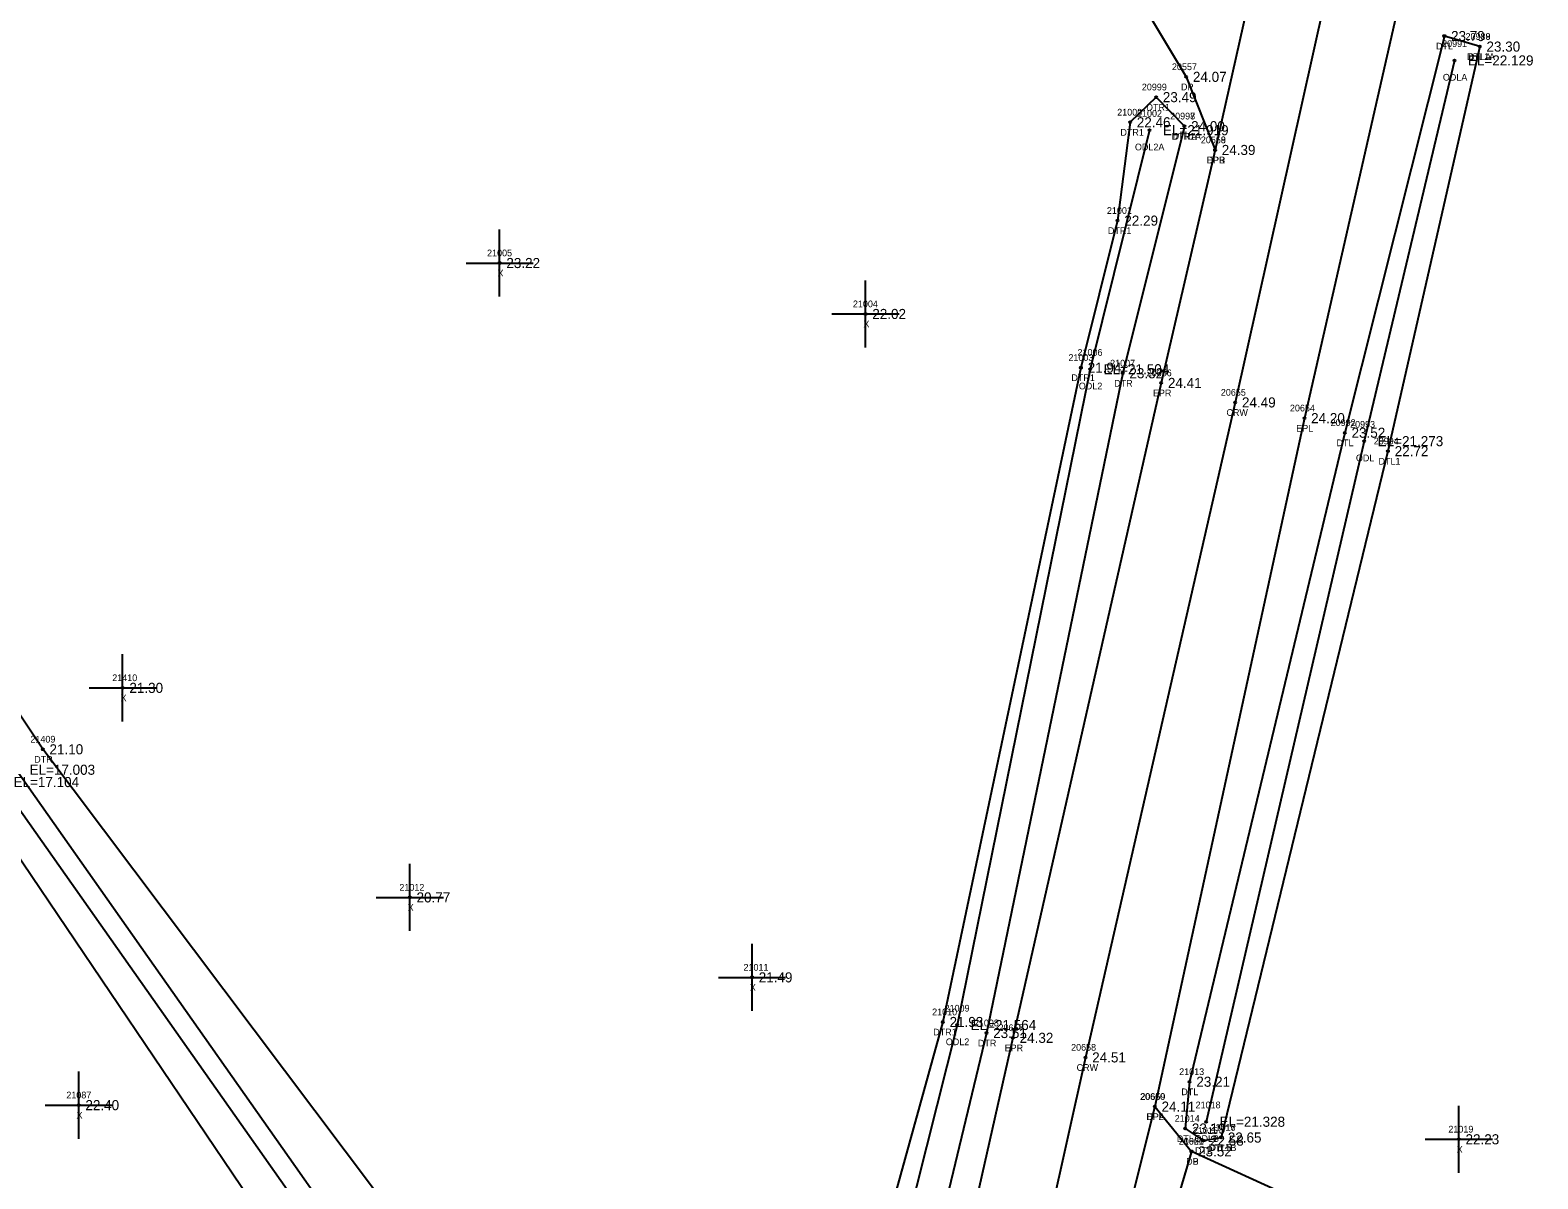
# Model space of a CAD drawing. Extents: x 2655177 to 2656219, y 761780 to 764748.
# Drawn here: x 2655371.8 to 2655596.2, y 762404.1 to 762575 of the extents above; entities that cross this region are included whole.
import ezdxf

# ---------------------------------------------------------------- set-up
doc = ezdxf.new("R2010")
doc.units = 0
for name, color, linetype in [('RD_DTM_BkLn1', 7, 'Continuous'), ('RD_EX_Driveway', 7, 'Continuous'), ('RD_EX_Driveway_txCode', 7, 'Continuous'), ('RD_EX_H2O', 7, 'Continuous'), ('RD_EX_H2O_txCode', 7, 'Continuous'), ('RD_EX_Misc', 7, 'Continuous'), ('RD_EX_Misc_txCode', 7, 'Continuous'), ('RD_EX_Road', 7, 'Continuous'), ('RD_EX_Road_txCode', 7, 'Continuous'), ('RD_EX_TX_Driveway_ELEV', 7, 'Continuous'), ('RD_EX_TX_H2O_ELEV', 7, 'Continuous'), ('RD_EX_TX_Misc_ELEV', 7, 'Continuous'), ('RD_EX_TX_Road_ELEV', 7, 'Continuous'), ('RD_HC_Survey_ELEV', 7, 'Continuous'), ('RD_HC_Survey_txCode', 7, 'Continuous'), ('RD_SMD_Locator', 7, 'Continuous')]:
    doc.layers.add(name, color=color, linetype=linetype)

msp = doc.modelspace()

# ---------------------------------------------------------------- linework, layer by layer
at = {"layer": 'RD_DTM_BkLn1'}
msp.add_lwpolyline([(2655711.06, 763230.3), (2655703.38, 763195.9), (2655681.97, 763099.65), (2655659.44, 762998.39), (2655637.72, 762903.26), (2655615.94, 762806.28), (2655593.94, 762710.45), (2655572.67, 762616.37), (2655551.12, 762519.58), (2655528.83, 762422.13), (2655507.58, 762326.81), (2655486.01, 762234.2), (2655464.77, 762141.12), (2655442.2, 762047.28), (2655420.99, 761952.95), (2655398.79, 761855.74), (2655384.11, 761791.21)], dxfattribs=at)
at = {"layer": 'RD_EX_Driveway'}
for points in [[(2655502.28, 762719.95), (2655507.82, 762714.48), (2655500.58, 762684.69), (2655497.67, 762681.01), (2655495.37, 762681.19), (2655493.84, 762671.94), (2655495.71, 762671.31), (2655495.21, 762667.77), (2655491.25, 762663.24), (2655487.93, 762656.49), (2655481.1, 762632.76), (2655485.71, 762616.62), (2655484.3, 762604.91), (2655505.68, 762598.43), (2655526.95, 762586.38), (2655538.16, 762577.45), (2655543.82, 762568.02), (2655548.11, 762557.14)], [(2655539.15, 762414.81), (2655544.59, 762408.15), (2655538.99, 762389.2), (2655531.98, 762386.15)], [(2655618.28, 762384.97), (2655560.02, 762401.08), (2655544.59, 762408.15)]]:
    msp.add_lwpolyline(points, dxfattribs=at)
at = {"layer": 'RD_EX_H2O'}
for points in [[(2655472.03, 762316.1), (2655422.66, 762374.06), (2655364.12, 762460.66), (2655307.09, 762538.82), (2655256.59, 762623.14), (2655196.27, 762713.84), (2655205.8, 762720.91)], [(2655477.51, 762339.55), (2655436.55, 762384.38), (2655373.64, 762467.97), (2655320.48, 762547.58), (2655269.92, 762633.7), (2655205.8, 762720.91)], [(2655476.38, 762321.27), (2655427.48, 762377.64), (2655367.29, 762463.1), (2655312.28, 762542.21), (2655260.75, 762626.43), (2655202.15, 762714.73)], [(2655477.37, 762324.35), (2655429.88, 762379.43), (2655369.67, 762464.93), (2655315.46, 762544.29), (2655265.61, 762630.28), (2655205.06, 762716.28)], [(2655587.51, 762572.52), (2655582.24, 762574.09), (2655567.43, 762515.07), (2655544.33, 762418.51), (2655543.66, 762411.55), (2655546.37, 762409.75), (2655549.01, 762410.21)], [(2655587.51, 762572.52), (2655573.85, 762512.33), (2655549.01, 762410.21)], [(2655583.75, 762570.46), (2655570.32, 762513.82), (2655546.78, 762412.56)], [(2655543.55, 762560.68), (2655539.34, 762565), (2655535.47, 762561.26), (2655533.61, 762546.63), (2655528.16, 762524.75), (2655507.6, 762427.4), (2655486.29, 762350.37), (2655477.51, 762339.55)], [(2655543.55, 762560.68), (2655534.37, 762523.92), (2655514.09, 762425.76), (2655491.38, 762331.28), (2655488.62, 762321.94), (2655478.48, 762315.45), (2655472.03, 762316.1)], [(2655538.37, 762560.08), (2655529.54, 762524.52), (2655509.74, 762426.95), (2655490.05, 762348.82), (2655482.81, 762330.14), (2655485.04, 762327.47), (2655476.38, 762321.27)]]:
    msp.add_lwpolyline(points, dxfattribs=at)
at = {"layer": 'RD_EX_Misc'}
for p, q in [((2655441.64, 762535.32), (2655441.64, 762545.32)), ((2655436.64, 762540.32), (2655446.64, 762540.32)), ((2655496.1, 762527.74), (2655496.1, 762537.74)), ((2655491.1, 762532.74), (2655501.1, 762532.74)), ((2655385.53, 762472.11), (2655385.53, 762482.11)), ((2655380.53, 762477.11), (2655390.53, 762477.11)), ((2655428.27, 762440.94), (2655428.27, 762450.94)), ((2655423.27, 762445.94), (2655433.27, 762445.94)), ((2655479.2, 762429.04), (2655479.2, 762439.04)), ((2655474.2, 762434.04), (2655484.2, 762434.04)), ((2655378.99, 762410.03), (2655378.99, 762420.03)), ((2655373.99, 762415.03), (2655383.99, 762415.03)), ((2655584.39, 762404.95), (2655584.39, 762414.95)), ((2655579.39, 762409.95), (2655589.39, 762409.95))]:
    msp.add_line(p, q, dxfattribs=at)
at = {"layer": 'RD_EX_Road'}
for points in [[(2655700.99, 763232.28), (2655693.55, 763198.57), (2655671.65, 763102.04), (2655649.04, 763001.06), (2655627.27, 762906.23), (2655605, 762809.37), (2655598.99, 762783.09), (2655583.65, 762714.14), (2655561.97, 762618.32), (2655556.36, 762593.84), (2655548.11, 762557.14), (2655540.1, 762522.48), (2655518.03, 762425.04), (2655496.48, 762329.56), (2655475.55, 762236.62), (2655473.2, 762226.14), (2655466.57, 762197.5), (2655460.06, 762168.16), (2655454.26, 762143.78), (2655432.5, 762049.88), (2655410.7, 761955.51), (2655388.17, 761858.43), (2655373.5, 761793.95)], [(2655576.46, 762583.32), (2655561.41, 762517.24), (2655539.15, 762414.81), (2655531.98, 762386.15), (2655517.98, 762324.29), (2655508.17, 762280.15), (2655501.46, 762251.6), (2655496.92, 762232.09), (2655477.2, 762144.97), (2655472.14, 762122.52), (2655453.74, 762045.1), (2655431.79, 761949.92), (2655409.76, 761853.25), (2655401.25, 761816.42), (2655394.61, 761787.37)]]:
    msp.add_lwpolyline(points, dxfattribs=at)
at = {"layer": 'RD_SMD_Locator'}
for centre in [(2655582.24, 762574.09), (2655587.51, 762572.52), (2655587.51, 762572.52), (2655583.75, 762570.46), (2655543.82, 762568.02), (2655539.34, 762565), (2655535.47, 762561.26), (2655538.37, 762560.08), (2655543.55, 762560.68), (2655543.55, 762560.68), (2655548.11, 762557.14), (2655548.11, 762557.14), (2655533.61, 762546.63), (2655441.64, 762540.32), (2655496.1, 762532.74), (2655528.16, 762524.75), (2655529.54, 762524.52), (2655534.37, 762523.92), (2655540.1, 762522.48), (2655551.12, 762519.58), (2655561.41, 762517.24), (2655567.43, 762515.07), (2655570.32, 762513.82), (2655573.85, 762512.33), (2655385.53, 762477.11), (2655373.64, 762467.97), (2655428.27, 762445.94), (2655479.2, 762434.04), (2655507.6, 762427.4), (2655509.74, 762426.95), (2655514.09, 762425.76), (2655518.03, 762425.04), (2655528.83, 762422.13), (2655544.33, 762418.51), (2655378.99, 762415.03), (2655539.15, 762414.81), (2655539.15, 762414.81), (2655543.66, 762411.55), (2655546.78, 762412.56), (2655546.37, 762409.75), (2655549.01, 762410.21), (2655549.01, 762410.21), (2655584.39, 762409.95), (2655544.59, 762408.15), (2655544.59, 762408.15)]:
    msp.add_circle(centre, 0.15, dxfattribs=at)

# ---------------------------------------------------------------- texts
at = {"layer": 'RD_EX_Driveway_txCode'}
for s, p in [('20557', (2655541.7, 762569.02)), ('DP', (2655543.04, 762566.02)), ('20558', (2655546, 762558.14)), ('DPB', (2655546.86, 762555.14)), ('20660', (2655536.95, 762415.81)), ('DPA', (2655537.89, 762412.81)), ('20661', (2655542.71, 762409.15)), ('21026', (2655542.74, 762409.15)), ('DP', (2655543.81, 762406.15)), ('DB', (2655543.81, 762406.15))]:
    msp.add_text(s, height=1, dxfattribs=at).set_placement(p)
at = {"layer": 'RD_EX_H2O_txCode'}
for s, p in [('20991', (2655581.91, 762572.46)), ('20988', (2655585.39, 762573.52)), ('20989', (2655585.39, 762573.52)), ('DTL', (2655581, 762572.09)), ('DTL1A', (2655585.62, 762570.52)), ('DTLA', (2655585.78, 762570.52)), ('20999', (2655537.22, 762566)), ('ODLA', (2655582.02, 762567.46)), ('21000', (2655533.55, 762562.26)), ('21002', (2655536.5, 762562.08)), ('DTR1', (2655537.91, 762563)), ('20997', (2655541.43, 762561.68)), ('20998', (2655541.43, 762561.68)), ('DTR1', (2655534.03, 762559.26)), ('ODL2A', (2655536.19, 762557.08)), ('DTR1A', (2655541.63, 762558.68)), ('DTRA', (2655541.8, 762558.68)), ('21001', (2655532.02, 762547.63)), ('DTR1', (2655532.17, 762544.63)), ('21003', (2655526.29, 762525.75)), ('21006', (2655527.64, 762526.52)), ('21007', (2655532.5, 762524.92)), ('DTR1', (2655526.73, 762522.75)), ('ODL2', (2655527.84, 762521.52)), ('DTR', (2655533.1, 762521.92)), ('20992', (2655565.32, 762516.07)), ('20993', (2655568.21, 762515.82)), ('DTL', (2655566.19, 762513.07)), ('20994', (2655571.73, 762513.33)), ('ODL', (2655569.08, 762510.82)), ('DTL1', (2655572.44, 762510.33)), ('21409', (2655371.8, 762468.97)), ('DTR', (2655372.37, 762465.97)), ('21009', (2655507.86, 762428.95)), ('21010', (2655506.01, 762428.4)), ('21008', (2655512.22, 762426.76)), ('DTR1', (2655506.17, 762425.4)), ('ODL2', (2655508.04, 762423.95)), ('DTR', (2655512.82, 762423.76)), ('21013', (2655542.78, 762419.51)), ('DTL', (2655543.09, 762416.51)), ('21018', (2655545.22, 762414.56)), ('21014', (2655542.11, 762412.55)), ('21015', (2655544.82, 762410.75)), ('21016', (2655547.43, 762411.21)), ('21017', (2655547.46, 762411.21)), ('DTL', (2655542.42, 762409.55)), ('ODLB', (2655545.06, 762409.56)), ('DTL', (2655545.13, 762407.75)), ('DTL1B', (2655547.13, 762408.21)), ('DTLB', (2655547.29, 762408.21))]:
    msp.add_text(s, height=1, dxfattribs=at).set_placement(p)
at = {"layer": 'RD_EX_Misc_txCode'}
for s, p in [('21005', (2655439.77, 762541.32)), ('X', (2655441.32, 762538.32)), ('21004', (2655494.22, 762533.74)), ('X', (2655495.78, 762530.74)), ('21410', (2655383.98, 762478.11)), ('X', (2655385.22, 762475.11)), ('21012', (2655426.72, 762446.94)), ('X', (2655427.95, 762443.94)), ('21011', (2655477.93, 762435.04)), ('X', (2655478.88, 762432.04)), ('21087', (2655377.15, 762416.03)), ('X', (2655378.67, 762413.03)), ('21019', (2655582.84, 762410.95)), ('X', (2655584.08, 762407.95))]:
    msp.add_text(s, height=1, dxfattribs=at).set_placement(p)
at = {"layer": 'RD_EX_Road_txCode'}
for s, p in [('20559', (2655546, 762558.14)), ('EPR', (2655546.89, 762555.14)), ('20656', (2655537.94, 762523.48)), ('EPR', (2655538.87, 762520.48)), ('20654', (2655559.26, 762518.24)), ('EPL', (2655560.2, 762515.24)), ('20657', (2655515.89, 762426.04)), ('EPR', (2655516.8, 762423.04)), ('20659', (2655537.01, 762415.81)), ('EPL', (2655537.95, 762412.81))]:
    msp.add_text(s, height=1, dxfattribs=at).set_placement(p)
at = {"layer": 'RD_EX_TX_Driveway_ELEV'}
for s, p in [('24.07', (2655544.82, 762567.27)), ('24.39', (2655549.11, 762556.39)), ('24.11', (2655540.15, 762414.06)), ('23.52', (2655545.59, 762407.4)), ('23.52', (2655545.59, 762407.4))]:
    msp.add_text(s, height=1.5, dxfattribs=at).set_placement(p)
at = {"layer": 'RD_EX_TX_H2O_ELEV'}
for s, p in [('23.79', (2655583.24, 762573.34)), ('23.30', (2655588.51, 762571.77)), ('23.30', (2655588.51, 762571.77)), ('EL=22.129', (2655585.75, 762569.71)), ('23.49', (2655540.34, 762564.25)), ('22.46', (2655536.47, 762560.51)), ('EL=21.919', (2655540.37, 762559.33)), ('24.00', (2655544.55, 762559.93)), ('24.00', (2655544.55, 762559.93)), ('22.29', (2655534.61, 762545.88)), ('21.94', (2655529.16, 762524)), ('EL=21.504', (2655531.54, 762523.77)), ('23.32', (2655535.37, 762523.17)), ('23.52', (2655568.43, 762514.32)), ('EL=21.273', (2655572.32, 762513.07)), ('22.72', (2655574.85, 762511.58)), ('21.10', (2655374.64, 762467.22)), ('EL=17.003', (2655371.67, 762464.18)), ('EL=17.104', (2655369.29, 762462.35)), ('21.93', (2655508.6, 762426.65)), ('EL=21.564', (2655511.74, 762426.2)), ('23.51', (2655515.09, 762425.01)), ('23.21', (2655545.33, 762417.76)), ('23.19', (2655544.66, 762410.8)), ('EL=21.328', (2655548.78, 762411.81)), ('22.58', (2655547.37, 762409)), ('22.65', (2655550.01, 762409.46)), ('22.65', (2655550.01, 762409.46))]:
    msp.add_text(s, height=1.5, dxfattribs=at).set_placement(p)
at = {"layer": 'RD_EX_TX_Misc_ELEV'}
for s, p in [('23.22', (2655442.64, 762539.57)), ('22.02', (2655497.1, 762531.99)), ('21.30', (2655386.53, 762476.36)), ('20.77', (2655429.27, 762445.19)), ('21.49', (2655480.2, 762433.29)), ('22.40', (2655379.99, 762414.28)), ('22.23', (2655585.39, 762409.2))]:
    msp.add_text(s, height=1.5, dxfattribs=at).set_placement(p)
at = {"layer": 'RD_EX_TX_Road_ELEV'}
for s, p in [('24.39', (2655549.11, 762556.39)), ('24.41', (2655541.1, 762521.73)), ('24.20', (2655562.41, 762516.49)), ('24.32', (2655519.03, 762424.29)), ('24.11', (2655540.15, 762414.06))]:
    msp.add_text(s, height=1.5, dxfattribs=at).set_placement(p)
at = {"layer": 'RD_HC_Survey_ELEV'}
for s, p in [('24.49', (2655552.12, 762518.83)), ('24.51', (2655529.83, 762421.38))]:
    msp.add_text(s, height=1.5, dxfattribs=at).set_placement(p)
at = {"layer": 'RD_HC_Survey_txCode'}
for s, p in [('20655', (2655548.98, 762520.58)), ('CRW', (2655549.81, 762517.58)), ('20658', (2655526.69, 762423.13)), ('CRW', (2655527.51, 762420.13))]:
    msp.add_text(s, height=1, dxfattribs=at).set_placement(p)

doc.saveas('drawing.dxf')
